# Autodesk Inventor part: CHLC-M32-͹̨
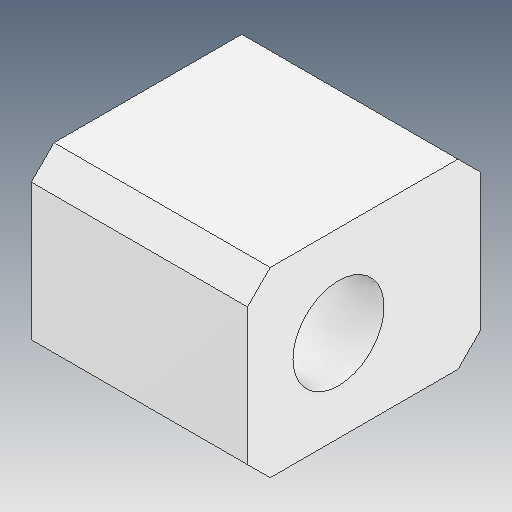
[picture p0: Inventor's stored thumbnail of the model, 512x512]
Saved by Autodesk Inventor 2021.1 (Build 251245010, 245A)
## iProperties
Created: 2021-05
Part Number: CHLC-M32-͹̨
Material: Ogólny
Document SubType Name: Modeling
Designer: user
Density: 1 g/cm^3
Appearance: Domyślna
Author: user
Revision Number: ÈÎºÎ
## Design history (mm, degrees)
feature "ÊäÈë1"
node "Bryła1"
